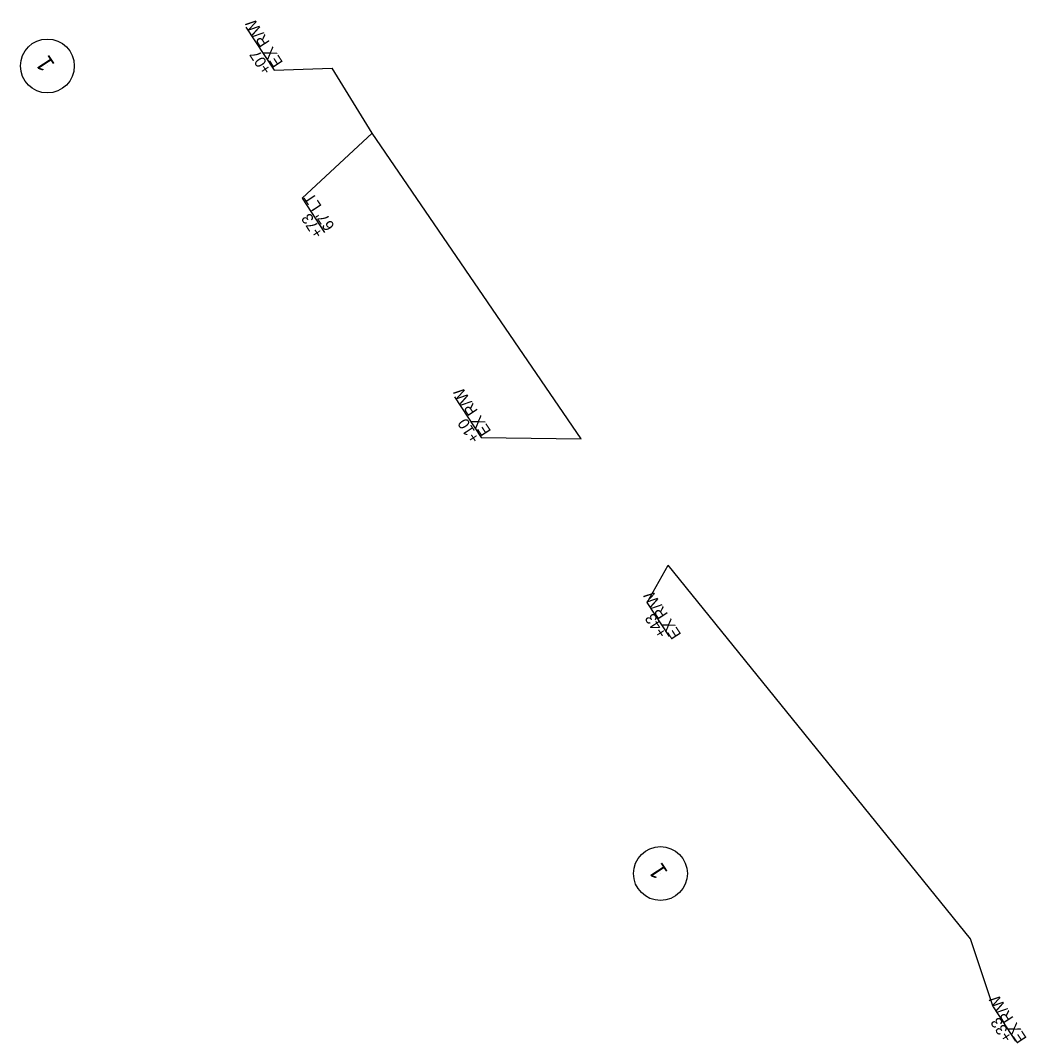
# Model space of a CAD drawing. Extents: x 1555582 to 1558054, y 687961 to 694065.
# Drawn here: x 1557605.6 to 1558053.9, y 687961 to 688416.9 of the extents above; entities that cross this region are included whole.
import ezdxf

# ---------------------------------------------------------------- set-up
doc = ezdxf.new("R2010")
doc.units = 0
for name, color, linetype in [('Exist Structure Minor Drop Inlet Text', 7, 'Continuous'), ('Prop Drainage Structure Box Reinforced Concrete', 7, 'Continuous'), ('Prop Drainage Structure Catch Basin Grate 840 03F Label', 7, 'Continuous'), ('Prop Drainage Structure Catch Basin Grate 840 03G CELL', 7, 'Continuous')]:
    doc.layers.add(name, color=color, linetype=linetype)

msp = doc.modelspace()

# ---------------------------------------------------------------- linework, layer by layer
at = {"layer": 'Exist Structure Minor Drop Inlet Text'}
for p, q in [((1557706, 688413.88), (1557718.57, 688394.72)), ((1557731.06, 688337.67), (1557741.05, 688322.43)), ((1557799.02, 688249.12), (1557810.86, 688231.06)), ((1557894.81, 688142.33), (1557884.81, 688157.57)), ((1558039.01, 687977.28), (1558049.01, 687962.04))]:
    msp.add_line(p, q, dxfattribs=at)
for points in [[(1557718.57, 688394.72), (1557744.54, 688395.61)], [(1557731.06, 688337.67), (1557762.27, 688366.6)], [(1557810.86, 688231.06), (1557855.39, 688230.51)], [(1557884.81, 688157.57), (1557894.14, 688174.16)], [(1558039.01, 687977.28), (1558028.88, 688007.64)]]:
    msp.add_lwpolyline(points, dxfattribs=at)
at = {"layer": 'Prop Drainage Structure Box Reinforced Concrete'}
for p, q in [((1557744.54, 688395.61), (1557744.55, 688395.59)), ((1557762.27, 688366.6), (1557744.54, 688395.61)), ((1557855.39, 688230.51), (1557762.27, 688366.6))]:
    msp.add_line(p, q, dxfattribs=at)
msp.add_lwpolyline([(1558028.88, 688007.64), (1557894.14, 688174.16)], dxfattribs=at)
at = {"layer": 'Prop Drainage Structure Catch Basin Grate 840 03F Label'}
for p, q in [((1557617.56, 688396.59), (1557617.56, 688396.59)), ((1557890.76, 688036.73), (1557890.76, 688036.73))]:
    msp.add_line(p, q, dxfattribs=at)
for centre in [(1557617.56, 688396.59), (1557890.76, 688036.73)]:
    msp.add_circle(centre, 12, dxfattribs=at)

# ---------------------------------------------------------------- texts
at = {"layer": 'Exist Structure Minor Drop Inlet Text'}
for s, p in [('EX R/W', (1557722.75, 688398.14)), ('+07', (1557717.73, 688394.85)), ("67' LT", (1557745.8, 688325.21)), ('+73', (1557740.78, 688321.92)), ('EX R/W', (1557815.48, 688233.87)), ('+10', (1557810.46, 688230.58)), ('EX R/W', (1557900.21, 688143.26)), ('+43', (1557893.89, 688143.68)), ('EX R/W', (1558054.21, 687963.27)), ('+33', (1558047.9, 687963.69))]:
    msp.add_text(s, height=5, rotation=123.2617, dxfattribs=at).set_placement(p)
at = {"layer": 'Prop Drainage Structure Catch Basin Grate 840 03G CELL'}
for p in [(1557621.13, 688397.23), (1557894.33, 688037.36)]:
    msp.add_text('1', height=7.5, rotation=123.2617, dxfattribs=at).set_placement(p)

doc.saveas('drawing.dxf')
